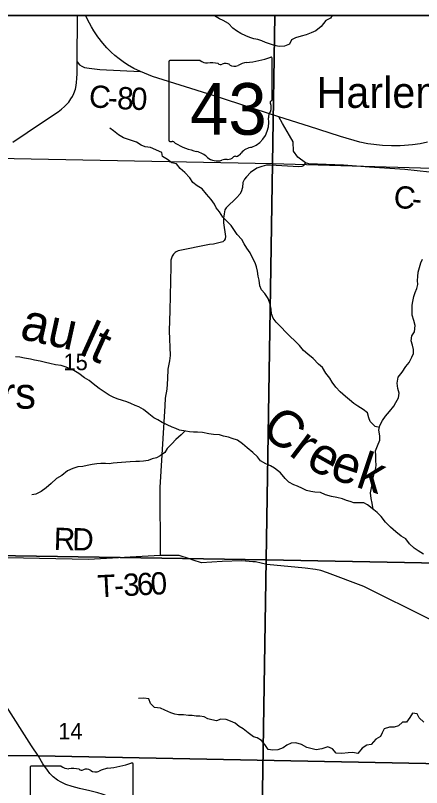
# Model space of a CAD drawing. Extents: x -20.5 to 34, y -66 to 23.9.
# Drawn here: x 3.275 to 4.312, y 18.93 to 20.9 of the extents above; entities that cross this region are included whole.
import ezdxf

# ---------------------------------------------------------------- set-up
doc = ezdxf.new("R2010")
doc.units = 0
for name, color, linetype in [('Default', 7, 'Continuous'), ('GM_X_County_Road_Text', 7, 'Continuous'), ('GM_X_County_Text', 7, 'Continuous'), ('GM_X_Minor_Lake', 7, 'Continuous'), ('GM_X_Minor_River_Text', 7, 'Continuous'), ('GM_X_Section_Text', 7, 'Continuous'), ('GM_X_State_Route', 7, 'Continuous'), ('GM_X_State_Shield', 7, 'Continuous'), ('GM_X_Township_Road', 7, 'Continuous'), ('GM_X_Township_Road_Text', 7, 'Continuous'), ('GM_X_Township_Text', 7, 'Continuous'), ('GM_X_Unincorporated', 7, 'Continuous'), ('GM_X_Unincorporated_Location', 7, 'Continuous'), ('SH_Cut_Line', 7, 'Continuous'), ('SH_Data', 7, 'Continuous')]:
    doc.layers.add(name, color=color, linetype=linetype)

msp = doc.modelspace()

# ---------------------------------------------------------------- linework, layer by layer
at = {"layer": 'Default'}
for points in [[(2.1, 20.9), (8.9, 20.9), (8.9, 14.1), (2.1, 14.1)], [(3.9378, 20.9), (2.9256, 20.9), (2.9181, 20.5414), (3.9312, 20.5222)], [(4.9548, 20.9), (3.9378, 20.9), (3.9312, 20.5222), (4.9488, 20.4926)]]:
    msp.add_lwpolyline(points, close=True, dxfattribs=at)
for points in [[(8.3774, 18.8452), (8.7292, 18.8379), (8.9, 18.8361), (8.9, 20.9), (2.1, 20.9), (2.1, 19.024), (2.1138, 19.0238), (2.8866, 19.0123), (2.9847, 19.0125), (3.3332, 19.0103), (5.1839, 18.9738), (5.2343, 18.9736), (5.2893, 18.9731), (5.9456, 18.969), (5.9451, 18.8918), (6.0429, 18.8899), (6.0928, 18.889), (6.2064, 18.8869)], [(6.2064, 18.8869), (6.0928, 18.889), (6.0429, 18.8899), (5.9451, 18.8918), (5.9456, 18.969), (5.2893, 18.9731), (5.2343, 18.9736), (5.1839, 18.9738), (3.3332, 19.0103), (2.9847, 19.0125), (2.8866, 19.0123), (2.8861, 18.9025), (2.8826, 18.5075), (2.8801, 18.0269), (2.88, 18.0245)]]:
    msp.add_lwpolyline(points, dxfattribs=at)
at = {"layer": 'GM_X_County_Text'}
for points in [[(4.0161, 20.5239), (4.0102, 20.5162), (4.0064, 20.5143), (3.9988, 20.5134), (3.9267, 20.5176), (3.9163, 20.5177), (3.9045, 20.5149), (3.8913, 20.5102), (3.8754, 20.4994), (3.8649, 20.4882), (3.8602, 20.4822), (3.856, 20.4737), (3.8546, 20.4607), (3.8514, 20.4496), (3.8484, 20.4439), (3.8401, 20.4355), (3.8134, 20.4091), (3.8101, 20.4043), (3.8079, 20.3937), (3.8066, 20.383), (3.8067, 20.3705), (3.8113, 20.336), (3.8103, 20.3299), (3.8079, 20.3256), (3.8046, 20.3222), (3.7979, 20.3206), (3.7804, 20.3162), (3.7701, 20.3157), (3.6905, 20.2991), (3.6889, 20.2984)], [(3.6889, 20.2984), (3.6855, 20.2968), (3.6826, 20.2947), (3.6785, 20.291), (3.6751, 20.2856), (3.6718, 20.2753), (3.672, 20.2594), (3.6688, 20.1469), (3.6672, 20.0952), (3.6699, 20.0318), (3.6685, 20.0185), (3.6642, 19.9972), (3.6634, 19.9729), (3.6618, 19.9459), (3.6575, 19.923), (3.6562, 19.9037), (3.6432, 19.695), (3.6446, 19.5218)], [(3.7291, 19.5099), (3.7219, 19.5123), (3.6932, 19.522), (3.6446, 19.5218), (3.4611, 19.5119), (3.1691, 19.5178)], [(3.8875, 19.5055), (3.8809, 19.5061), (3.8528, 19.5083), (3.8033, 19.5063), (3.7497, 19.503), (3.7291, 19.5099)], [(4.5355, 19.254), (4.5337, 19.2547), (4.4928, 19.272), (4.3325, 19.3596), (4.1651, 19.4428), (4.0724, 19.4774), (4.055, 19.4834), (4.0413, 19.4858), (4.0152, 19.4898), (3.9166, 19.4987), (3.8884, 19.5055), (3.8875, 19.5055)]]:
    msp.add_lwpolyline(points, dxfattribs=at)
at = {"layer": 'GM_X_Minor_Lake'}
for points in [[(2.9181, 20.5414), (3.9312, 20.5222), (3.9151, 19.5111), (2.9013, 19.5268)], [(3.9312, 20.5222), (4.9488, 20.4926), (4.9304, 19.491), (3.9151, 19.5111)], [(3.9151, 19.5111), (3.8987, 18.493), (2.8841, 18.5113), (2.9013, 19.5268)], [(3.9151, 19.5111), (4.9304, 19.491), (4.9118, 18.4742), (3.8987, 18.493)]]:
    msp.add_lwpolyline(points, close=True, dxfattribs=at)
at = {"layer": 'GM_X_Minor_River_Text'}
for points in [[(3.9365, 20.8234), (3.924, 20.8277), (3.9134, 20.8306), (3.9038, 20.835), (3.8943, 20.8387), (3.8837, 20.8401), (3.8738, 20.8437), (3.8636, 20.8478), (3.8502, 20.854), (3.8399, 20.8611), (3.83, 20.8678), (3.8188, 20.8794), (3.8058, 20.8871), (3.7959, 20.8912), (3.7837, 20.8986), (3.7813, 20.9)], [(4.0837, 20.9), (4.0793, 20.8932), (4.068, 20.887), (4.0554, 20.872), (4.0423, 20.8609), (4.0299, 20.8554), (4.0175, 20.8507), (4.0043, 20.8471), (3.9904, 20.8427), (3.9802, 20.8376), (3.9751, 20.8269), (3.9619, 20.8214), (3.9487, 20.8205), (3.9365, 20.8234)], [(4.2045, 19.8481), (4.1934, 19.8508), (4.1807, 19.8635), (4.1776, 19.8733), (4.174, 19.8858), (4.1633, 19.8948), (4.1495, 19.9033), (4.1392, 19.91), (4.1281, 19.9193), (4.1177, 19.9279), (4.1047, 19.9391), (4.0932, 19.951), (4.0839, 19.9646), (4.0777, 19.9743), (4.0681, 19.9871), (4.0592, 20.0014), (4.0492, 20.01), (4.0354, 20.0249), (4.022, 20.0358), (4.0105, 20.0451), (4.0008, 20.0575), (3.9647, 20.0926), (3.9547, 20.1038), (3.9406, 20.1169), (3.9332, 20.1274), (3.9289, 20.1387), (3.9283, 20.1501), (3.9251, 20.1633), (3.92, 20.1773), (3.9115, 20.1901), (3.9034, 20.1998), (3.8991, 20.2104), (3.8974, 20.2244), (3.8949, 20.2346), (3.8929, 20.2471), (3.8904, 20.2584), (3.8869, 20.269), (3.8791, 20.2833), (3.8744, 20.2938), (3.8655, 20.3062), (3.8593, 20.3171), (3.8534, 20.3281), (3.8415, 20.3408), (3.8323, 20.3539), (3.8261, 20.3641), (3.8157, 20.3738), (3.8049, 20.3854), (3.7957, 20.3989), (3.7879, 20.4087), (3.7829, 20.4185), (3.7748, 20.4301), (3.7625, 20.4436), (3.752, 20.4571), (3.7387, 20.4649), (3.7276, 20.4735), (3.7202, 20.4859), (3.7079, 20.499), (3.6957, 20.5098), (3.6864, 20.521), (3.6743, 20.5239), (3.6632, 20.5325), (3.6502, 20.5403), (3.6489, 20.5505), (3.6196, 20.5626), (3.6063, 20.5651), (3.5957, 20.5691), (3.5838, 20.5765), (3.5739, 20.5802), (3.5633, 20.583), (3.5507, 20.5878), (3.5378, 20.5956), (3.5255, 20.6053), (3.5156, 20.6127)], [(4.1888, 19.6392), (4.1865, 19.6554), (4.1836, 19.6671), (4.1819, 19.6819), (4.1851, 19.6986), (4.1876, 19.7097), (4.1889, 19.7199), (4.1914, 19.7313), (4.1946, 19.7416), (4.1964, 19.7519), (4.1958, 19.7648), (4.1953, 19.7765), (4.1947, 19.789), (4.1994, 19.8016), (4.2053, 19.8161), (4.2059, 19.8275), (4.203, 19.8415), (4.2058, 19.854), (4.2125, 19.8662), (4.2199, 19.877), (4.2303, 19.8892), (4.2411, 19.9027), (4.247, 19.9122), (4.2532, 19.9244), (4.2553, 19.9359), (4.2517, 19.9479), (4.25, 19.9616), (4.2528, 19.9768), (4.2625, 19.9894), (4.2725, 20.004), (4.2807, 20.0143), (4.2873, 20.0277), (4.2917, 20.0376), (4.2919, 20.0479), (4.2891, 20.0588), (4.2855, 20.0694), (4.2872, 20.0823), (4.2946, 20.093), (4.2959, 20.1086), (4.2923, 20.1218), (4.2879, 20.135), (4.2882, 20.1468), (4.2883, 20.1608), (4.2897, 20.1703), (4.2925, 20.1832), (4.2962, 20.1928), (4.3006, 20.2035), (4.3031, 20.213), (4.3018, 20.2236), (4.3024, 20.2338), (4.3037, 20.2448), (4.307, 20.257), (4.3106, 20.2684), (4.315, 20.278)], [(4.3174, 19.5253), (4.304, 19.5342), (4.293, 19.5405), (4.2818, 19.5517), (4.2718, 19.5641), (4.26, 19.5715), (4.2466, 19.5823), (4.2328, 19.5946), (4.2201, 19.6073), (4.2089, 19.6216), (4.1989, 19.6313), (4.1859, 19.6414), (4.1744, 19.6511), (4.1649, 19.6566), (4.1524, 19.6565), (4.1395, 19.6566), (4.13, 19.6596), (4.1202, 19.6624), (4.1099, 19.6665), (4.0955, 19.6697), (4.0818, 19.6722), (4.0666, 19.6769), (4.054, 19.6824), (4.0396, 19.6833), (4.029, 19.6851), (4.018, 19.6879), (4.0081, 19.6927), (3.9955, 19.6986), (3.986, 19.7019), (3.9734, 19.7089), (3.9638, 19.7187), (3.9515, 19.7325), (3.937, 19.7448), (3.9263, 19.7511), (3.9141, 19.7559), (3.9008, 19.7637), (3.893, 19.7734), (3.8811, 19.785), (3.867, 19.7966), (3.8551, 19.8067), (3.8421, 19.8163), (3.8284, 19.8203), (3.8189, 19.8236), (3.806, 19.8268), (3.7961, 19.8297), (3.781, 19.8303), (3.7688, 19.8324), (3.7525, 19.8356), (3.74, 19.8369), (3.7298, 19.8368), (3.7196, 19.8374), (3.7101, 19.8388), (3.6942, 19.842), (3.6843, 19.8456), (3.6748, 19.8496), (3.6626, 19.8555), (3.65, 19.8614), (3.6386, 19.8681), (3.6283, 19.8729), (3.6153, 19.8833), (3.6015, 19.8941), (3.59, 19.9016), (3.5805, 19.9048), (3.5699, 19.9096), (3.5592, 19.914), (3.5482, 19.9177), (3.5345, 19.9213), (3.5246, 19.9257), (3.5143, 19.9312), (3.499, 19.9412), (3.4887, 19.9479), (3.473, 19.9598), (3.4627, 19.9684), (3.4512, 19.9755), (3.4371, 19.9866), (3.4237, 19.994), (3.4142, 19.9985), (3.4039, 20.0021), (3.3918, 20.0065), (3.377, 20.0082), (3.3622, 20.0118), (3.3512, 20.0143), (3.3379, 20.0175), (3.3231, 20.0203), (3.3128, 20.0228), (3.298, 20.0257), (3.2863, 20.0282), (3.2745, 20.0288)], [(3.7079, 19.8392), (3.6978, 19.8299), (3.6843, 19.8183), (3.6746, 19.8072), (3.6627, 19.7952), (3.6564, 19.7849), (3.6448, 19.7764), (3.6351, 19.7713), (3.6238, 19.7682), (3.614, 19.7642), (3.6015, 19.7622), (3.5917, 19.762), (3.5819, 19.7615), (3.5679, 19.7609), (3.5565, 19.7604), (3.546, 19.7591), (3.5346, 19.7586), (3.5241, 19.7577), (3.5142, 19.756), (3.5044, 19.7566), (3.4927, 19.7569), (3.4828, 19.7556), (3.4704, 19.7539), (3.4579, 19.7518), (3.4466, 19.749), (3.4338, 19.7481), (3.421, 19.7441), (3.4078, 19.7382), (3.3929, 19.7263), (3.3794, 19.7181), (3.3659, 19.7054), (3.3536, 19.6942), (3.3405, 19.685), (3.3266, 19.6783), (3.3168, 19.6763)], [(4.3183, 19.0966), (4.3064, 19.1074), (4.3013, 19.1175), (4.2888, 19.1192), (4.2822, 19.1081), (4.2741, 19.0966), (4.2638, 19.0964), (4.253, 19.0872), (4.2425, 19.0839), (4.2308, 19.0837), (4.2168, 19.0797), (4.2117, 19.0698), (4.2073, 19.0602), (4.1957, 19.0528), (4.1834, 19.0393), (4.1725, 19.038), (4.1609, 19.0299), (4.1498, 19.0164), (4.1365, 19.0192), (4.1248, 19.0186), (4.1085, 19.0165), (4.0945, 19.0174), (4.0845, 19.0286), (4.073, 19.0333), (4.0572, 19.0288), (4.0432, 19.0256), (4.0292, 19.0295), (4.0193, 19.032), (4.0052, 19.0397), (3.9911, 19.0436), (3.9794, 19.0427), (3.9685, 19.0383), (3.9584, 19.0313), (3.9452, 19.0258), (3.932, 19.0248), (3.9206, 19.0269), (3.912, 19.04), (3.9032, 19.0497), (3.8924, 19.0563), (3.8829, 19.0592), (3.8695, 19.0692), (3.8568, 19.0792), (3.8465, 19.0859), (3.8358, 19.094), (3.8239, 19.0995), (3.8133, 19.1031), (3.7996, 19.1044), (3.7883, 19.1001), (3.7766, 19.1029), (3.7663, 19.1054), (3.7568, 19.1098), (3.7461, 19.1115), (3.7367, 19.1121), (3.7264, 19.1134), (3.7169, 19.114), (3.7037, 19.1153), (3.6916, 19.1155), (3.6821, 19.1172), (3.6714, 19.1208), (3.6565, 19.127), (3.6455, 19.1321), (3.6303, 19.1337), (3.6199, 19.1446), (3.6151, 19.1562), (3.603, 19.1579), (3.589, 19.1573)]]:
    msp.add_lwpolyline(points, dxfattribs=at)
at = {"layer": 'GM_X_State_Route'}
for points in [[(3.4324, 20.7819), (3.4384, 20.7739), (3.4442, 20.7704), (3.4515, 20.7674), (3.4628, 20.7651), (3.4907, 20.7618), (3.594, 20.7567)], [(4.5042, 20.542), (4.4975, 20.5279), (4.4907, 20.5186), (4.4837, 20.5128), (4.4772, 20.5081), (4.4685, 20.5062), (4.4571, 20.5042), (4.4497, 20.5024), (4.4091, 20.4992), (4.3969, 20.4979), (4.3878, 20.4967), (4.3777, 20.4963), (4.3639, 20.4968), (4.2699, 20.507), (4.1797, 20.5131), (4.1131, 20.5179), (4.0245, 20.5214), (4.0161, 20.5239), (3.9958, 20.5385), (3.985, 20.5535), (3.9843, 20.5773), (3.9751, 20.594), (3.9566, 20.6245), (3.9473, 20.6414)]]:
    msp.add_lwpolyline(points, dxfattribs=at)
at = {"layer": 'GM_X_Township_Road'}
for points in [[(3.2679, 20.5764), (3.3045, 20.6014), (3.3619, 20.6398), (3.3835, 20.6544), (3.3923, 20.6608), (3.4004, 20.6675), (3.4114, 20.6789), (3.4166, 20.6869), (3.4203, 20.6934), (3.4238, 20.7009), (3.4279, 20.712), (3.4297, 20.721), (3.4304, 20.7287), (3.4312, 20.7392), (3.432, 20.7514), (3.4324, 20.7642), (3.4324, 20.7819), (3.4331, 20.9)], [(4.3276, 20.5765), (4.3088, 20.5727), (4.2888, 20.5698), (4.2686, 20.5681), (4.2577, 20.5676), (4.2352, 20.567), (4.2128, 20.5682), (4.1751, 20.5726), (4.1543, 20.5767), (4.105, 20.5907), (4.0763, 20.6002), (4.0258, 20.6164), (3.9473, 20.6414), (3.9183, 20.651), (3.7798, 20.6954), (3.6245, 20.744), (3.594, 20.7567), (3.5776, 20.7646), (3.5611, 20.7742), (3.5499, 20.7816), (3.5394, 20.7892), (3.5286, 20.798), (3.519, 20.8066), (3.5079, 20.8177), (3.4979, 20.8289), (3.4852, 20.8453), (3.4746, 20.861), (3.4687, 20.871), (3.4638, 20.8801), (3.4591, 20.8894), (3.4556, 20.8975), (3.4547, 20.9)], [(3.6569, 18.7622), (3.6478, 18.7683), (3.6187, 18.7993), (3.5678, 18.8582), (3.5345, 18.891), (3.5213, 18.9008), (3.5078, 18.9084), (3.496, 18.9131), (3.4853, 18.9161), (3.4645, 18.9212), (3.4388, 18.9275), (3.4197, 18.9322), (3.4034, 18.9377), (3.3919, 18.9431), (3.3821, 18.9489), (3.3709, 18.9574), (3.363, 18.9658), (3.3568, 18.9737), (3.3446, 18.9905), (3.3334, 19.0098), (3.3161, 19.0363), (3.2459, 19.1458)]]:
    msp.add_lwpolyline(points, dxfattribs=at)
at = {"layer": 'GM_X_Unincorporated'}
for p, q in [((3.9306, 20.6852), (3.9306, 20.7899)), ((3.667, 20.7815), (3.667, 20.5814)), ((3.7468, 20.785), (3.6696, 20.785)), ((3.9306, 20.6853), (3.9306, 20.6852)), ((3.312, 18.9807), (3.312, 18.7806)), ((3.3918, 18.9841), (3.3146, 18.9841)), ((3.5756, 18.8844), (3.5756, 18.9891))]:
    msp.add_line(p, q, dxfattribs=at)
for centre, radius, start, end in [((3.8367, 21.0578), 0.2796, 275.8445, 288.9065), ((3.9277, 20.7904), 0.00294, 351.8621, 97.738), ((3.67, 20.782), 0.00305, 98.1301, 188.1301), ((3.7652, 20.8082), 0.0296, 231.6195, 271.1119), ((3.775, 20.6726), 0.1064, 80.4867, 94.9883), ((3.7991, 20.783), 0.00855, 219.7921, 297.1024), ((3.8117, 20.7599), 0.0178, 54.4667, 119.1411), ((3.8346, 20.7916), 0.0214, 233.8562, 294.8282), ((3.8724, 20.7239), 0.0563, 97.3462, 120.7689), ((3.93, 20.6776), 0.00454, 107.944, 210.337), ((3.9011, 20.6643), 0.0273, 340.033, 23.6496), ((3.9275, 20.6848), 0.00314, 289.6038, 7.7341), ((3.9411, 20.6414), 0.0198, 136.8065, 186.9296), ((3.8524, 20.6281), 0.0699, 292.3089, 8.9858), ((3.67, 20.581), 0.00308, 171.9584, 258.3066), ((3.6705, 20.6014), 0.0235, 267.339, 280.6039), ((3.6753, 20.5699), 0.00848, 29.7484, 93.2717), ((3.7824, 20.7497), 0.2019, 240.4129, 257.1985), ((3.7222, 20.4915), 0.0632, 47.1842, 75.836), ((3.8819, 20.5252), 0.0383, 94.4031, 142.5768), ((3.7905, 20.5689), 0.0401, 230.7004, 286.2918), ((3.8136, 20.4997), 0.0329, 85.6951, 111.2099), ((3.8166, 20.5539), 0.0214, 268.777, 315.5493), ((3.8359, 20.5345), 0.00601, 65.7517, 132.6484), ((3.8333, 20.562), 0.0226, 282.8732, 323.2771), ((3.315, 18.9811), 0.00305, 98.1301, 188.1301), ((3.4102, 19.0074), 0.0296, 231.6195, 271.1119), ((3.42, 18.8718), 0.1064, 80.4867, 94.9883), ((3.4441, 18.9822), 0.00855, 219.7921, 297.1024), ((3.4567, 18.959), 0.0178, 54.4667, 119.1411), ((3.4796, 18.9908), 0.0214, 233.8562, 294.8282), ((3.5174, 18.923), 0.0563, 97.3462, 120.7689), ((3.4817, 19.257), 0.2796, 275.8445, 288.9065), ((3.5727, 18.9895), 0.00294, 351.8621, 97.738)]:
    msp.add_arc(centre, radius, start, end, dxfattribs=at)
at = {"layer": 'SH_Cut_Line'}
msp.add_lwpolyline([(8.0662, 14.9881), (8.0784, 15.8902), (8.0825, 16.3121), (8.087, 16.6605), (8.0955, 17.3258), (8.2289, 17.3235), (8.271, 17.3227), (8.5216, 17.3182), (8.9, 17.3115), (8.9, 20.9), (2.1, 20.9), (2.1, 14.4131)], dxfattribs=at)
at = {"layer": 'SH_Data'}
msp.add_line((2.1, 20.9), (8.9, 20.9), dxfattribs=at)

# ---------------------------------------------------------------- texts
at = {"layer": 'GM_X_County_Road_Text'}
for s, height, rotation, p in [('au', 0.09471, 347.5466, (3.2833, 20.0755)), ('lt', 0.09471, 335.5492, (3.434, 20.0367)), ('Cr', 0.0947, 322.6978, (3.8977, 19.8358)), ('e', 0.0947, 330.6968, (4.0127, 19.751)), ('ek', 0.09471, 341.6947, (4.0743, 19.7202))]:
    msp.add_text(s, height=height, rotation=rotation, dxfattribs=at).set_placement(p)
at = {"layer": 'GM_X_Section_Text'}
for s, rotation, p in [('R', 358.419, (3.3721, 19.5364)), ('D', 359.2664, (3.4196, 19.5351)), ('T', 2.9048, (3.4856, 19.4148)), ('3', 2.8842, (3.5514, 19.4181)), ('6', 2.8138, (3.5863, 19.4199)), ('0', 2.306, (3.6211, 19.4216)), ('-', 2.9049, (3.5281, 19.4169))]:
    msp.add_text(s, height=0.0568, rotation=rotation, dxfattribs=at).set_placement(p)
at = {"layer": 'GM_X_State_Shield'}
for s, height, p in [('Harlem Springs', 0.078977, (4.044, 20.6641)), ('Corners', 0.07898, (2.9515, 19.8966))]:
    msp.add_text(s, height=height, rotation=0, dxfattribs=at).set_placement(p)
at = {"layer": 'GM_X_Township_Road_Text'}
for s, rotation, p in [('C', 354.6137, (3.4605, 20.6669)), ('8', 357.5964, (3.5335, 20.6612)), ('0', 357.7127, (3.5686, 20.6597)), ('-', 357.3117, (3.5098, 20.6623)), ('C', 354.2156, (4.239, 20.4101)), ('-', 354.295, (4.2855, 20.4053))]:
    msp.add_text(s, height=0.0568, rotation=rotation, dxfattribs=at).set_placement(p)
at = {"layer": 'GM_X_Township_Text'}
for s, p in [('15', (3.3973, 19.9947)), ('14', (3.384, 19.0528))]:
    msp.add_text(s, height=0.04186, rotation=0, dxfattribs=at).set_placement(p)
at = {"layer": 'GM_X_Unincorporated'}
msp.add_text('43', height=0.13184, dxfattribs=at).set_placement((3.7206, 20.5955))
at = {"layer": 'GM_X_Unincorporated_Location'}
for s in ['s', 'r']:
    msp.add_text(s, height=0.000189, dxfattribs=at).set_placement((3.7958, 20.6682))
msp.add_text('43', height=0.000189, rotation=0, dxfattribs=at).set_placement((3.7481, 20.6544))

doc.saveas('drawing.dxf')
